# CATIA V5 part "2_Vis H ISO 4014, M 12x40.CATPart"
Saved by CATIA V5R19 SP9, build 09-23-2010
Part number: 2_Vis H ISO 4014, M 12x40
Revision: ANY
Definition: UNKNOWN
Nomenclature: 2_Vis H ISO 4014, M 12x40
Source: Unknown
Bounding box of the stored display mesh (mm): x -10.392 to 10.392, y -40 to 7.5, z -9 to 9
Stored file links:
  Y:\fin de projet cabestan poupee\2_Vis H ISO 4014, M 12x40.CATPart
  Ass_arbre poupee_1.CATProduct
  Y:\bricolage cabestan\6_axe.CATPart
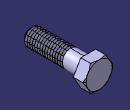
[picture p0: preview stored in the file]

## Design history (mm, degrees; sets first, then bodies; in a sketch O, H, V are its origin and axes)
Body1 "NONE" (main body)
  Solid1: solid without history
